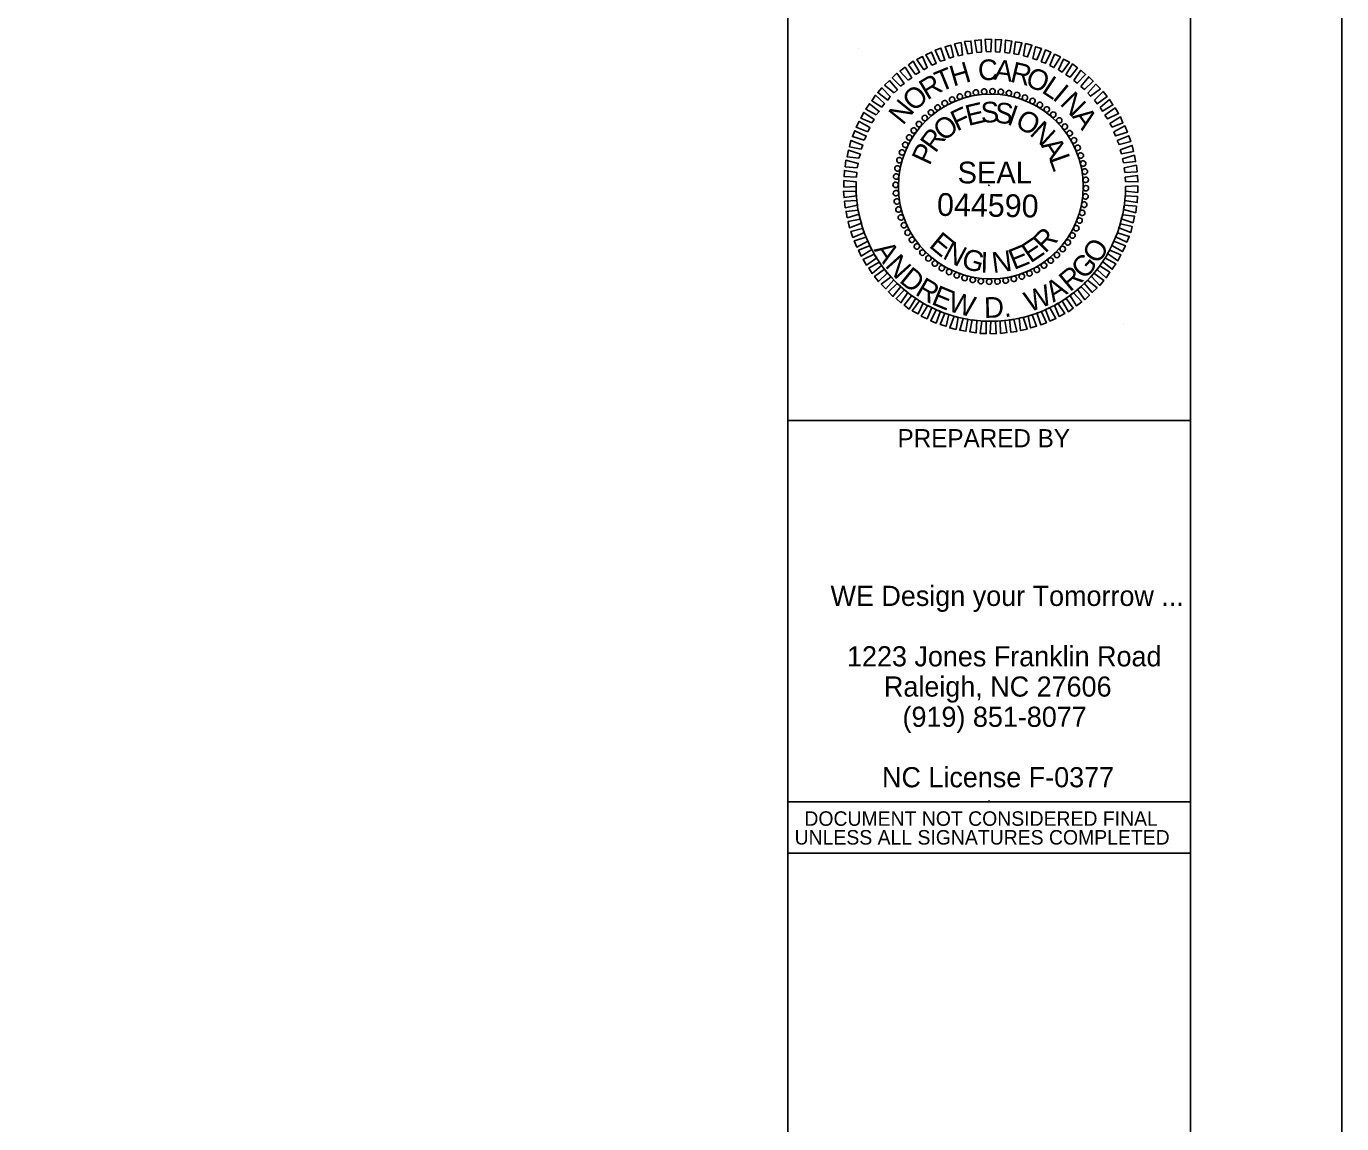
# Model space of a CAD drawing. Extents: x 0 to 3.05, y 0 to 1.83.
# Drawn here: x 2.289 to 2.833, y 0.917 to 1.371 of the extents above; entities that cross this region are included whole.
import ezdxf

# ---------------------------------------------------------------- set-up
doc = ezdxf.new("R2010")
doc.units = 0
for name, color, linetype in [('Draft_Construction', 7, 'Continuous'), ('Scratch_Level_1', 7, 'Continuous'), ('Scratch_Level_3', 7, 'Continuous'), ('Scratch_Level_5', 7, 'Continuous'), ('Sheet Border Standard 30in CELL', 7, 'Continuous'), ('Sheet Plan CELL', 7, 'Continuous'), ('Sheet_PE_Note_CELL', 7, 'Continuous'), ('Sheet_Plan_CELL', 7, 'Continuous')]:
    doc.layers.add(name, color=color, linetype=linetype)

msp = doc.modelspace()

# ---------------------------------------------------------------- linework, layer by layer
at = {"layer": 'Draft_Construction'}
for radius, start, end in [(0.03822, 0, 180), (0.05574, 180, 0), (0.03822, 180, 0)]:
    msp.add_arc((2.68817, 1.30425), radius, start, end, dxfattribs=at)
at = {"layer": 'Scratch_Level_1'}
for p, q in [((2.60412, 0.0625), (2.60416, 1.77083)), ((2.77079, 0.0625), (2.77083, 1.77083))]:
    msp.add_line(p, q, dxfattribs=at)
for points in [[(2.77079, 0.0625), (0.0625, 0.0625), (0.0625, 1.77083), (2.77079, 1.77083)], [(2.60422, 1.20743), (2.77079, 1.20743), (2.77079, 1.04972), (2.60422, 1.04972)]]:
    msp.add_lwpolyline(points, close=True, dxfattribs=at)
at = {"layer": 'Scratch_Level_3'}
msp.add_line((2.83333, 0), (2.83333, 1.83333), dxfattribs=at)
at = {"layer": 'Scratch_Level_5'}
for p, q in [((2.63332, 1.3614), (2.63332, 1.3614)), ((2.74301, 1.2471), (2.74301, 1.2471))]:
    msp.add_line(p, q, dxfattribs=at)
msp.add_circle((2.68737, 1.30476), 0.0001, dxfattribs=at)
msp.add_circle((2.68737, 1.30476), 0.0001, dxfattribs=at)
msp.add_circle((2.68737, 1.30476), 0.0001, dxfattribs=at)
at = {"layer": 'Sheet Border Standard 30in CELL'}
msp.add_lwpolyline([(2.60413, 1.04972), (2.77079, 1.04972), (2.77079, 1.0285), (2.60413, 1.0285)], close=True, dxfattribs=at)
at = {"layer": 'Sheet Plan CELL'}
msp.add_line((2.77079, 1.04972), (2.60413, 1.04972), dxfattribs=at)
at = {"layer": 'Sheet_PE_Note_CELL'}
for p, q in [((2.67216, 1.34026), (2.67216, 1.34026)), ((2.6753, 1.34151), (2.6753, 1.34151)), ((2.67859, 1.34246), (2.67859, 1.34246)), ((2.68205, 1.34308), (2.68205, 1.34308)), ((2.68542, 1.34355), (2.68542, 1.34355)), ((2.68887, 1.34363), (2.68887, 1.34363)), ((2.69232, 1.3434), (2.69232, 1.3434)), ((2.6957, 1.34285), (2.6957, 1.34285)), ((2.69899, 1.34214), (2.69899, 1.34214)), ((2.70229, 1.34104), (2.70229, 1.34104)), ((2.70543, 1.33963), (2.70543, 1.33963)), ((2.66337, 1.33492), (2.66337, 1.33492)), ((2.66612, 1.33689), (2.66612, 1.33689)), ((2.6691, 1.33869), (2.6691, 1.33869)), ((2.70849, 1.33806), (2.70849, 1.33806)), ((2.71131, 1.3361), (2.71131, 1.3361)), ((2.71406, 1.33398), (2.71406, 1.33398)), ((2.65843, 1.33014), (2.65843, 1.33014)), ((2.66078, 1.33257), (2.66078, 1.33257)), ((2.71649, 1.33163), (2.71649, 1.33163)), ((2.71884, 1.32904), (2.71884, 1.32904)), ((2.65435, 1.32457), (2.65435, 1.32457)), ((2.65631, 1.32739), (2.65631, 1.32739)), ((2.7208, 1.32629), (2.7208, 1.32629)), ((2.72261, 1.32331), (2.72261, 1.32331)), ((2.65137, 1.31837), (2.65137, 1.31837)), ((2.65278, 1.32151), (2.65278, 1.32151)), ((2.72418, 1.32025), (2.72418, 1.32025)), ((2.72543, 1.31712), (2.72543, 1.31712)), ((2.64957, 1.31178), (2.64957, 1.31178)), ((2.65027, 1.31508), (2.65027, 1.31508)), ((2.72637, 1.31382), (2.72637, 1.31382)), ((2.64902, 1.30841), (2.64902, 1.30841)), ((2.727, 1.31037), (2.727, 1.31037)), ((2.72747, 1.30699), (2.72747, 1.30699)), ((2.64878, 1.30495), (2.64878, 1.30495)), ((2.64886, 1.3015), (2.64886, 1.3015)), ((2.68817, 1.30425), (2.68817, 1.30425)), ((2.72755, 1.30354), (2.72755, 1.30354)), ((2.64933, 1.29813), (2.64933, 1.29813)), ((2.72677, 1.29672), (2.72677, 1.29672)), ((2.72731, 1.30009), (2.72731, 1.30009)), ((2.64996, 1.29468), (2.64996, 1.29468)), ((2.6509, 1.29138), (2.6509, 1.29138)), ((2.72496, 1.29013), (2.72496, 1.29013)), ((2.72606, 1.29342), (2.72606, 1.29342)), ((2.65215, 1.28824), (2.65215, 1.28824)), ((2.65372, 1.28518), (2.65372, 1.28518)), ((2.72355, 1.28699), (2.72355, 1.28699)), ((2.65553, 1.2822), (2.65553, 1.2822)), ((2.65749, 1.27946), (2.65749, 1.27946)), ((2.72002, 1.2811), (2.72002, 1.2811)), ((2.72198, 1.28393), (2.72198, 1.28393)), ((2.65984, 1.27687), (2.65984, 1.27687)), ((2.66228, 1.27451), (2.66228, 1.27451)), ((2.71296, 1.27357), (2.71296, 1.27357)), ((2.71555, 1.27593), (2.71555, 1.27593)), ((2.7179, 1.27836), (2.7179, 1.27836)), ((2.66502, 1.2724), (2.66502, 1.2724)), ((2.66785, 1.27043), (2.66785, 1.27043)), ((2.67091, 1.26887), (2.67091, 1.26887)), ((2.70417, 1.26824), (2.70417, 1.26824)), ((2.70723, 1.26981), (2.70723, 1.26981)), ((2.71021, 1.27161), (2.71021, 1.27161)), ((2.67404, 1.26745), (2.67404, 1.26745)), ((2.67734, 1.26636), (2.67734, 1.26636)), ((2.68063, 1.26565), (2.68063, 1.26565)), ((2.68401, 1.2651), (2.68401, 1.2651)), ((2.68746, 1.26486), (2.68746, 1.26486)), ((2.69091, 1.26494), (2.69091, 1.26494)), ((2.69429, 1.26541), (2.69429, 1.26541)), ((2.69774, 1.26604), (2.69774, 1.26604)), ((2.70103, 1.26698), (2.70103, 1.26698))]:
    msp.add_line(p, q, dxfattribs=at)
for points in [[(2.66722, 1.35603), (2.66518, 1.36058), (2.66753, 1.36152), (2.66918, 1.3565)], [(2.67106, 1.35728), (2.66926, 1.36199), (2.67169, 1.3627), (2.67271, 1.35783)], [(2.67483, 1.3583), (2.67318, 1.36325), (2.67585, 1.3638), (2.67648, 1.3587)], [(2.67859, 1.35917), (2.67734, 1.36419), (2.67993, 1.36442), (2.68048, 1.3594)], [(2.68236, 1.35964), (2.6815, 1.36466), (2.68416, 1.36497), (2.68424, 1.35987)], [(2.68628, 1.36003), (2.68589, 1.36513), (2.68848, 1.36505), (2.68817, 1.35995)], [(2.69005, 1.35995), (2.69005, 1.36505), (2.69264, 1.36497), (2.69193, 1.35987)], [(2.69397, 1.35972), (2.69429, 1.36482), (2.69687, 1.36435), (2.69585, 1.3594)], [(2.69774, 1.35909), (2.69844, 1.36411), (2.70103, 1.36372), (2.69962, 1.35885)], [(2.70174, 1.35823), (2.70252, 1.36333), (2.70519, 1.3627), (2.70339, 1.35783)], [(2.7055, 1.35721), (2.70668, 1.36207), (2.70911, 1.36129), (2.70715, 1.35666)], [(2.70903, 1.35579), (2.71084, 1.36074), (2.71304, 1.35979), (2.71084, 1.35524)], [(2.65694, 1.35054), (2.65404, 1.35454), (2.65608, 1.35603), (2.65867, 1.35148)], [(2.66039, 1.3525), (2.65749, 1.35673), (2.65992, 1.35799), (2.66188, 1.35344)], [(2.66377, 1.35438), (2.66126, 1.35877), (2.66369, 1.35987), (2.66549, 1.35509)], [(2.71256, 1.3543), (2.71453, 1.35893), (2.71696, 1.35783), (2.71429, 1.35344)], [(2.71617, 1.3525), (2.71829, 1.35697), (2.72065, 1.35564), (2.71766, 1.35156)], [(2.65082, 1.34575), (2.64737, 1.3492), (2.64925, 1.35109), (2.65231, 1.34685)], [(2.65396, 1.34818), (2.65059, 1.35195), (2.6527, 1.3536), (2.65545, 1.3492)], [(2.71923, 1.35038), (2.72198, 1.35493), (2.72402, 1.35328), (2.72096, 1.34944)], [(2.72245, 1.34803), (2.72535, 1.35234), (2.72739, 1.35062), (2.72394, 1.34693)], [(2.72543, 1.34559), (2.72865, 1.34967), (2.73053, 1.34779), (2.72692, 1.34442)], [(2.64549, 1.34002), (2.64141, 1.34308), (2.64313, 1.34512), (2.64658, 1.34144)], [(2.64823, 1.34301), (2.64423, 1.34622), (2.64619, 1.34803), (2.64949, 1.34426)], [(2.72826, 1.34285), (2.73163, 1.34654), (2.73351, 1.34465), (2.72943, 1.34159)], [(2.64313, 1.33704), (2.6389, 1.33971), (2.64039, 1.34199), (2.64415, 1.33853)], [(2.731, 1.34002), (2.73461, 1.34355), (2.73626, 1.34144), (2.7321, 1.33846)], [(2.73336, 1.33696), (2.7372, 1.34026), (2.73869, 1.33798), (2.7343, 1.33547)], [(2.6389, 1.33053), (2.63442, 1.33249), (2.6356, 1.33492), (2.63984, 1.33202)], [(2.64078, 1.3339), (2.63639, 1.33626), (2.63795, 1.33846), (2.64203, 1.33532)], [(2.7354, 1.33375), (2.73955, 1.33673), (2.74104, 1.33438), (2.73649, 1.33218)], [(2.63733, 1.32692), (2.63246, 1.32873), (2.63364, 1.33116), (2.63811, 1.32865)], [(2.73744, 1.3303), (2.74183, 1.33304), (2.74285, 1.33061), (2.73838, 1.32881)], [(2.739, 1.32692), (2.74363, 1.32928), (2.74465, 1.32677), (2.73979, 1.3252)], [(2.63458, 1.3197), (2.62972, 1.32072), (2.63027, 1.32331), (2.63521, 1.32135)], [(2.63576, 1.32347), (2.63089, 1.32488), (2.63191, 1.32731), (2.63662, 1.32512)], [(2.74042, 1.32323), (2.7452, 1.32527), (2.74607, 1.32284), (2.7412, 1.32159)], [(2.63356, 1.31594), (2.6287, 1.31657), (2.62925, 1.31923), (2.63419, 1.31759)], [(2.74167, 1.31947), (2.74669, 1.32127), (2.74716, 1.31868), (2.74222, 1.31782)], [(2.74261, 1.3157), (2.74756, 1.31719), (2.74803, 1.31453), (2.74308, 1.31406)], [(2.63293, 1.31194), (2.62791, 1.31241), (2.62823, 1.31508), (2.63333, 1.31382)], [(2.74332, 1.31194), (2.74842, 1.31304), (2.74865, 1.31037), (2.74363, 1.31005)], [(2.63246, 1.30425), (2.62736, 1.30401), (2.62736, 1.30668), (2.63246, 1.30613)], [(2.63254, 1.30817), (2.62744, 1.30833), (2.6276, 1.31092), (2.6327, 1.31005)], [(2.74379, 1.30817), (2.74889, 1.3088), (2.74905, 1.30613), (2.74395, 1.30629)], [(2.63254, 1.30033), (2.62744, 1.2997), (2.62728, 1.30237), (2.63238, 1.30221)], [(2.74387, 1.30425), (2.74897, 1.30448), (2.74897, 1.30182), (2.74387, 1.30237)], [(2.63301, 1.29656), (2.62791, 1.29546), (2.62768, 1.29813), (2.6327, 1.29844)], [(2.7434, 1.29656), (2.74842, 1.29609), (2.7481, 1.29342), (2.74301, 1.29468)], [(2.74379, 1.30033), (2.74889, 1.30017), (2.74873, 1.29758), (2.74363, 1.29844)], [(2.63372, 1.29279), (2.62878, 1.2913), (2.6283, 1.29397), (2.63325, 1.29444)], [(2.63466, 1.28903), (2.62964, 1.28722), (2.62917, 1.28981), (2.63411, 1.29068)], [(2.74277, 1.29256), (2.74763, 1.29193), (2.74709, 1.28926), (2.74214, 1.29091)], [(2.63591, 1.28526), (2.63113, 1.28322), (2.63027, 1.28566), (2.63513, 1.28691)], [(2.74057, 1.28503), (2.74544, 1.28362), (2.74442, 1.28118), (2.73971, 1.28338)], [(2.74175, 1.28879), (2.74661, 1.28777), (2.74607, 1.28518), (2.74112, 1.28715)], [(2.63733, 1.28158), (2.6327, 1.27922), (2.63168, 1.28173), (2.63654, 1.2833)], [(2.6389, 1.2782), (2.6345, 1.27546), (2.63348, 1.27789), (2.63795, 1.27969)], [(2.739, 1.28158), (2.74387, 1.27977), (2.74269, 1.27734), (2.73822, 1.27985)], [(2.64094, 1.27475), (2.63678, 1.27177), (2.63529, 1.27412), (2.63984, 1.27632)], [(2.73555, 1.27459), (2.73995, 1.27224), (2.73838, 1.27004), (2.7343, 1.27318)], [(2.73744, 1.27797), (2.74191, 1.27601), (2.74073, 1.27357), (2.73649, 1.27648)], [(2.64298, 1.27153), (2.63913, 1.26824), (2.63764, 1.27051), (2.64203, 1.27302)], [(2.64533, 1.26847), (2.64172, 1.26494), (2.64007, 1.26706), (2.64423, 1.27004)], [(2.73084, 1.26847), (2.73492, 1.26541), (2.7332, 1.26337), (2.72975, 1.26706)], [(2.7332, 1.27145), (2.73744, 1.26879), (2.73594, 1.26651), (2.73218, 1.26996)], [(2.64808, 1.26565), (2.6447, 1.26196), (2.64282, 1.26384), (2.6469, 1.2669)], [(2.6509, 1.2629), (2.64768, 1.25882), (2.6458, 1.26071), (2.64941, 1.26408)], [(2.72551, 1.26275), (2.72896, 1.25929), (2.72708, 1.25741), (2.72402, 1.26165)], [(2.7281, 1.26549), (2.7321, 1.26228), (2.73014, 1.26047), (2.72684, 1.26424)], [(2.65388, 1.26047), (2.65098, 1.25616), (2.64894, 1.25788), (2.65239, 1.26157)], [(2.6571, 1.25812), (2.65435, 1.25357), (2.65231, 1.25521), (2.65537, 1.25906)], [(2.71939, 1.25796), (2.72229, 1.25396), (2.72025, 1.25247), (2.71766, 1.25702)], [(2.72237, 1.26031), (2.72575, 1.25655), (2.72363, 1.2549), (2.72088, 1.25929)], [(2.66016, 1.256), (2.65804, 1.25153), (2.65569, 1.25286), (2.65867, 1.25694)], [(2.66377, 1.25419), (2.6618, 1.24957), (2.65937, 1.25066), (2.66204, 1.25506)], [(2.6673, 1.2527), (2.66549, 1.24776), (2.6633, 1.2487), (2.66549, 1.25325)], [(2.67083, 1.25129), (2.66965, 1.24643), (2.66722, 1.24721), (2.66918, 1.25184)], [(2.70911, 1.25247), (2.71115, 1.24792), (2.7088, 1.24698), (2.70715, 1.252)], [(2.71256, 1.25412), (2.71508, 1.24972), (2.71264, 1.24862), (2.71084, 1.25341)], [(2.71594, 1.256), (2.71884, 1.25176), (2.71641, 1.25051), (2.71445, 1.25506)], [(2.67459, 1.25027), (2.67381, 1.24517), (2.67114, 1.2458), (2.67295, 1.25066)], [(2.67859, 1.24941), (2.67789, 1.24439), (2.6753, 1.24478), (2.67671, 1.24964)], [(2.68236, 1.24878), (2.68205, 1.24368), (2.67946, 1.24415), (2.68048, 1.2491)], [(2.68628, 1.24855), (2.68628, 1.24345), (2.68369, 1.24352), (2.6844, 1.24862)], [(2.69005, 1.24847), (2.69044, 1.24337), (2.68785, 1.24345), (2.68817, 1.24855)], [(2.69397, 1.24886), (2.69483, 1.24384), (2.69217, 1.24352), (2.69209, 1.24862)], [(2.69774, 1.24933), (2.69899, 1.24431), (2.6964, 1.24407), (2.69585, 1.2491)], [(2.7015, 1.25019), (2.70315, 1.24525), (2.70048, 1.2447), (2.69986, 1.2498)], [(2.70527, 1.25121), (2.70707, 1.24651), (2.70464, 1.2458), (2.70362, 1.25066)]]:
    msp.add_lwpolyline(points, close=True, dxfattribs=at)
for centre, major_axis in [((2.68201, 1.34312), (-0.00018, 0.00112)), ((2.68542, 1.34351), (-0.00008, 0.00113)), ((2.68885, 1.3436), (0.00002, 0.00113)), ((2.69228, 1.34339), (0.00012, 0.00112)), ((2.66909, 1.33867), (-0.000548, 0.000988)), ((2.67216, 1.3402), (-0.00046, 0.00103)), ((2.67535, 1.34146), (-0.00037, 0.00107)), ((2.67865, 1.34243), (-0.00027, 0.0011)), ((2.69567, 1.34288), (0.00022, 0.00111)), ((2.69901, 1.34208), (0.00031, 0.00109)), ((2.70227, 1.34099), (0.0004, 0.00105)), ((2.70542, 1.33962), (0.0005, 0.00102)), ((2.70843, 1.33798), (0.000582, 0.000968)), ((2.66083, 1.33256), (-0.000785, 0.000813)), ((2.6634, 1.33483), (-0.000711, 0.000878)), ((2.66616, 1.33687), (-0.000632, 0.000937)), ((2.7113, 1.33609), (0.000664, 0.000914)), ((2.71398, 1.33395), (0.000741, 0.000853)), ((2.65633, 1.32738), (-0.000914, 0.000664)), ((2.65847, 1.33007), (-0.000853, 0.000741)), ((2.71647, 1.33159), (0.000813, 0.000785)), ((2.71875, 1.32901), (0.000878, 0.000711)), ((2.6528, 1.3215), (-0.00102, 0.0005)), ((2.65443, 1.32452), (-0.000968, 0.000582)), ((2.72079, 1.32625), (0.000937, 0.000632)), ((2.72258, 1.32333), (0.000988, 0.000548)), ((2.65143, 1.31835), (-0.00105, 0.0004)), ((2.72412, 1.32026), (0.00103, 0.00046)), ((2.72537, 1.31706), (0.00107, 0.00037)), ((2.64954, 1.31176), (-0.00111, 0.00022)), ((2.65034, 1.3151), (-0.00109, 0.00031)), ((2.72635, 1.31377), (0.0011, 0.00027)), ((2.72703, 1.3104), (0.00112, 0.00018)), ((2.64903, 1.30836), (-0.00112, 0.00012)), ((2.72742, 1.30699), (0.00113, 0.00008)), ((2.64882, 1.30494), (-0.00113, 0.00002)), ((2.64891, 1.3015), (-0.00113, -0.00008)), ((2.7273, 1.30014), (0.00112, -0.00012)), ((2.72751, 1.30356), (0.00113, -0.00002)), ((2.6493, 1.29809), (-0.00112, -0.00018)), ((2.64998, 1.29473), (-0.0011, -0.00027)), ((2.7268, 1.29674), (0.00111, -0.00022)), ((2.65096, 1.29144), (-0.00107, -0.00037)), ((2.7249, 1.29015), (0.00105, -0.0004)), ((2.72599, 1.2934), (0.00109, -0.00031)), ((2.65221, 1.28824), (-0.00103, -0.00046)), ((2.65375, 1.28517), (-0.000988, -0.000548)), ((2.7219, 1.28398), (0.000968, -0.000582)), ((2.72354, 1.287), (0.00102, -0.0005)), ((2.65554, 1.28224), (-0.000937, -0.000632)), ((2.65758, 1.27948), (-0.000878, -0.000711)), ((2.71787, 1.27843), (0.000853, -0.000741)), ((2.72, 1.28112), (0.000914, -0.000664)), ((2.65986, 1.27691), (-0.000813, -0.000785)), ((2.66235, 1.27455), (-0.000741, -0.000853)), ((2.66503, 1.27241), (-0.000664, -0.000914)), ((2.71293, 1.27367), (0.000711, -0.000878)), ((2.7155, 1.27594), (0.000785, -0.000813)), ((2.6679, 1.27052), (-0.000582, -0.000968)), ((2.67091, 1.26888), (-0.0005, -0.00102)), ((2.67406, 1.26751), (-0.0004, -0.00105)), ((2.70098, 1.26704), (0.00037, -0.00107)), ((2.70417, 1.2683), (0.00046, -0.00103)), ((2.70724, 1.26983), (0.000548, -0.000988)), ((2.71017, 1.27162), (0.000632, -0.000937)), ((2.67732, 1.26642), (-0.00031, -0.00109)), ((2.68066, 1.26562), (-0.00022, -0.00111)), ((2.68405, 1.26511), (-0.00012, -0.00112)), ((2.68748, 1.2649), (-0.00002, -0.00113)), ((2.69091, 1.26499), (0.00008, -0.00113)), ((2.69432, 1.26538), (0.00018, -0.00112)), ((2.69769, 1.26606), (0.00027, -0.0011))]:
    msp.add_ellipse(centre, major_axis=major_axis, ratio=0.999708, dxfattribs=at)
at = {"layer": 'Sheet_Plan_CELL'}
msp.add_line((2.77088, 1.20743), (2.60422, 1.20743), dxfattribs=at)
for centre in [(2.68737, 1.30476), (2.68737, 1.30476), (2.68737, 1.30476), (2.68746, 1.05011)]:
    msp.add_circle(centre, 0.0001, dxfattribs=at)

# ---------------------------------------------------------------- texts
at = {"layer": 'Sheet Border Standard 30in CELL'}
for s, height, rotation, p in [('H', 0.00855, 16.2881, (2.67261, 1.34555)), ('C', 0.00855, 1.4832, (2.68295, 1.34814)), ('A', 0.00855, 352.5864, (2.68922, 1.34849)), ('R', 0.00855, 346.666, (2.69581, 1.34767)), ('R', 0.00855, 30.9582, (2.66187, 1.3398)), ('T', 0.00855, 22.179, (2.66722, 1.34324)), ('O', 0.00855, 337.821, (2.70196, 1.34615)), ('L', 0.00855, 326.1343, (2.7088, 1.3434)), ('O', 0.00855, 42.5191, (2.65642, 1.33485)), ('I', 0.00855, 320.353, (2.71329, 1.34058)), ('N', 0.00855, 51.0517, (2.65182, 1.3293)), ('N', 0.00855, 314.6222, (2.71641, 1.33828)), ('A', 0.00855, 306.1346, (2.72153, 1.33319)), ('A', 0.00855, 303.7312, (2.63956, 1.27812)), ('O', 0.00855, 56.7858, (2.73259, 1.27179)), ('N', 0.00855, 312.0437, (2.64406, 1.27138)), ('G', 0.00855, 48.0147, (2.72689, 1.26541)), ('D', 0.00855, 320.9399, (2.6499, 1.26497)), ('R', 0.00855, 40.015, (2.72091, 1.26042)), ('R', 0.00855, 329.5703, (2.65645, 1.25969)), ('E', 0.00855, 337.5701, (2.66316, 1.25573)), ('W', 0.00855, 20.6694, (2.70406, 1.25213)), ('A', 0.00855, 31.7025, (2.71402, 1.25616)), ('W', 0.00855, 345.0903, (2.66992, 1.25288)), ('D', 0.00855, 1.3504, (2.68544, 1.24989)), ('.', 0.00855, 9.9808, (2.69384, 1.25011)), ('DOCUMENT NOT CONSIDERED FINAL', 0.006, 0, (2.61104, 1.03985)), ('UNLESS ALL SIGNATURES COMPLETED', 0.006, 0, (2.60699, 1.03209))]:
    msp.add_text(s, height=height, rotation=rotation, dxfattribs=at).set_placement(p)
at = {"layer": 'Sheet Plan CELL'}
for s, p in [('WE Design your Tomorrow ...', (2.62186, 1.13079)), ('1223 Jones Franklin Road', (2.62868, 1.10579)), ('Raleigh, NC 27606', (2.64395, 1.09329)), ('(919) 851-8077', (2.65164, 1.08079)), ('NC License F-0377', (2.64316, 1.05579))]:
    msp.add_text(s, height=0.0083333, rotation=0, dxfattribs=at).set_placement(p)
at = {"layer": 'Sheet_PE_Note_CELL'}
for s, height, rotation, p in [('E', 0.00855, 13.334, (2.6788, 1.32926)), ('S', 0.00855, 1.4832, (2.68409, 1.33065)), ('S', 0.00855, 352.5864, (2.68929, 1.33082)), ('F', 0.00855, 25.1139, (2.67413, 1.32693)), ('I', 0.00855, 340.7633, (2.69445, 1.33012)), ('O', 0.00855, 331.9594, (2.69777, 1.32916)), ('R', 0.00855, 53.8654, (2.66523, 1.31777)), ('O', 0.00855, 39.647, (2.66873, 1.32256)), ('N', 0.00855, 317.4809, (2.70385, 1.32582)), ('A', 0.00855, 303.3373, (2.70877, 1.32114)), ('P', 0.00855, 64.9491, (2.66282, 1.31261)), ('L', 0.00855, 289.6205, (2.71214, 1.3159)), ('044590', 0.009415, 359, (2.66584, 1.29215)), ('E', 0.00855, 320.353, (2.66219, 1.27948)), ('R', 0.00855, 45.3778, (2.71073, 1.27636)), ('N', 0.00855, 331.9594, (2.66779, 1.27471)), ('E', 0.00855, 22.179, (2.69773, 1.26966)), ('E', 0.00855, 33.8657, (2.70458, 1.27233)), ('G', 0.00855, 343.7119, (2.67552, 1.27081)), ('I', 0.00855, 358.5168, (2.68381, 1.2687)), ('N', 0.00855, 7.4136, (2.68913, 1.26843))]:
    msp.add_text(s, height=height, rotation=rotation, dxfattribs=at).set_placement(p)
msp.add_text('SEAL', height=0.009, dxfattribs=at).set_placement((2.6744, 1.30553))
at = {"layer": 'Sheet_Plan_CELL'}
msp.add_text('PREPARED BY', height=0.0075, rotation=0, dxfattribs=at).set_placement((2.64958, 1.19641))

doc.saveas('drawing.dxf')
